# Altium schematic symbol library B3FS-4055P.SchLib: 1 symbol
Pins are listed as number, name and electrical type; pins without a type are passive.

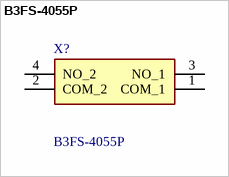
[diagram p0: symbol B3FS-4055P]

## B3FS-4055P
designator X?
Switch Tactile N.O. SPST Projected Plunger Gull Wing 0.05A 24VDC 2.55N SMD T/R; Manufacturer_Name: OMRON Electronics; Geometry.Height: 7.3mm
footprint B3FS4055P
pins: 1 COM_1, 2 COM_2, 3 NO_1, 4 NO_2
